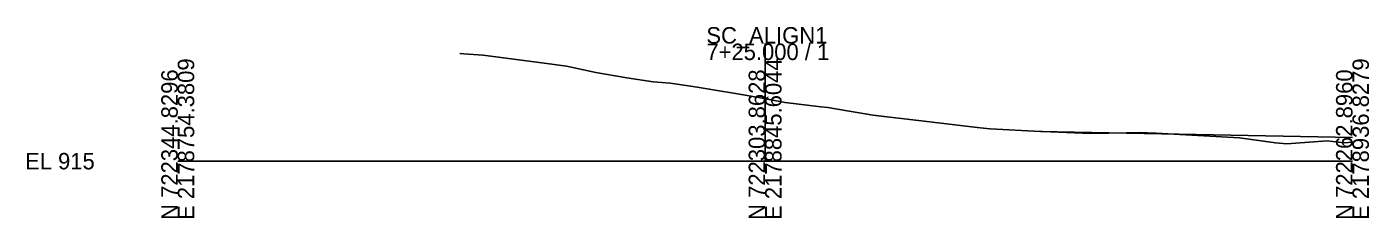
# Model space of a CAD drawing. Extents: x -2342 to 14913, y -10 to 5257.
# Drawn here: x 1974.3 to 2202.8, y 4490.3 to 4522.8 of the extents above; entities that cross this region are included whole.
import ezdxf

# ---------------------------------------------------------------- set-up
doc = ezdxf.new("R2010")
doc.units = 0
for name, color, linetype in [('Default', 7, 'Continuous'), ('GK_Cells', 7, 'Continuous'), ('SC_Scratch1', 7, 'Continuous'), ('XS_X_Ground_Line', 7, 'Continuous')]:
    doc.layers.add(name, color=color, linetype=linetype)

msp = doc.modelspace()

# ---------------------------------------------------------------- linework, layer by layer
at = {"layer": 'GK_Cells'}
for p, q in [((2100, 4500), (2100, 4520)), ((2000, 4500), (2100, 4500)), ((2100, 4500), (2200, 4500))]:
    msp.add_line(p, q, dxfattribs=at)
at = {"layer": 'SC_Scratch1'}
msp.add_lwpolyline([(2048.05, 4518.27), (2048.09, 4518.29), (2048.7, 4518.24), (2051.93, 4518.05), (2052.86, 4517.94), (2058.05, 4517.26), (2061.98, 4516.74), (2066.18, 4516.18), (2071.18, 4515.09), (2076.46, 4514.19), (2080.93, 4513.51), (2083.83, 4513.29), (2087.38, 4512.75), (2089.09, 4512.49), (2090.5, 4512.27), (2095.97, 4511.32), (2099.48, 4510.73), (2103.39, 4509.97), (2109.47, 4509.22), (2110.66, 4509.1), (2114.31, 4508.52), (2117.36, 4507.97), (2118.35, 4507.85), (2127.09, 4506.81), (2136.08, 4505.75), (2137.2, 4505.61), (2138.29, 4505.52), (2146.89, 4505.04), (2146.92, 4505.04), (2149.72, 4504.99), (2200, 4504.02)], dxfattribs=at)
at = {"layer": 'XS_X_Ground_Line'}
msp.add_lwpolyline([(2048.05, 4518.27), (2048.09, 4518.29), (2048.7, 4518.24), (2051.93, 4518.05), (2052.86, 4517.94), (2058.05, 4517.26), (2061.98, 4516.74), (2066.18, 4516.18), (2071.18, 4515.09), (2076.46, 4514.19), (2080.93, 4513.51), (2083.83, 4513.29), (2087.38, 4512.75), (2089.09, 4512.49), (2090.5, 4512.27), (2095.97, 4511.32), (2099.48, 4510.73), (2103.39, 4509.97), (2109.47, 4509.22), (2110.66, 4509.1), (2114.31, 4508.52), (2117.36, 4507.97), (2118.35, 4507.85), (2127.09, 4506.81), (2136.08, 4505.75), (2137.2, 4505.61), (2138.29, 4505.52), (2146.89, 4505.04), (2147.24, 4505.03), (2155.38, 4504.68), (2161.5, 4504.84), (2163.7, 4504.85), (2166.6, 4504.78), (2180.79, 4503.99), (2186.9, 4503.1), (2188.84, 4502.96), (2195.69, 4503.48), (2198.61, 4503.1), (2200, 4503.22)], dxfattribs=at)

# ---------------------------------------------------------------- texts
at = {"layer": 'Default'}
msp.add_text('-', height=0.0001, dxfattribs=at).set_placement((2000, 4500))
at = {"layer": 'GK_Cells'}
for s, p in [('SC_ALIGN1', (2090, 4520)), ('7+25.000 / 1', (2090, 4517.2)), ('EL 915', (1974, 4498.6))]:
    msp.add_text(s, height=2.8, dxfattribs=at).set_placement(p)
for s, p in [('E 2178754.3809', (2002.8, 4490)), ('E 2178845.6044', (2102.8, 4490)), ('E 2178936.8279', (2202.8, 4490)), ('N 722344.8296', (2000, 4490)), ('N 722303.8628', (2100, 4490)), ('N 722262.8960', (2200, 4490))]:
    msp.add_text(s, height=2.8, rotation=90, dxfattribs=at).set_placement(p)
at = {"layer": 'SC_Scratch1'}
msp.add_text('X', height=0.0001, dxfattribs=at).set_placement((2100, 4510.63))

doc.saveas('drawing.dxf')
